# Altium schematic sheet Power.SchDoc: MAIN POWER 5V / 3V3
size A4; Date: Not used; ApprovedBy: Not used; CheckedBy: Not used; Author: Not used; CompanyName: STMicroelectronics; DrawnBy: Not used; Engineer: Not used; Organization: Not used; Address1: Not used; Address2: Not used; Address3: Not used; Address4: Not used; DocumentNumber: 6; Revision: Not used; SheetNumber: 6; SheetTotal: 8
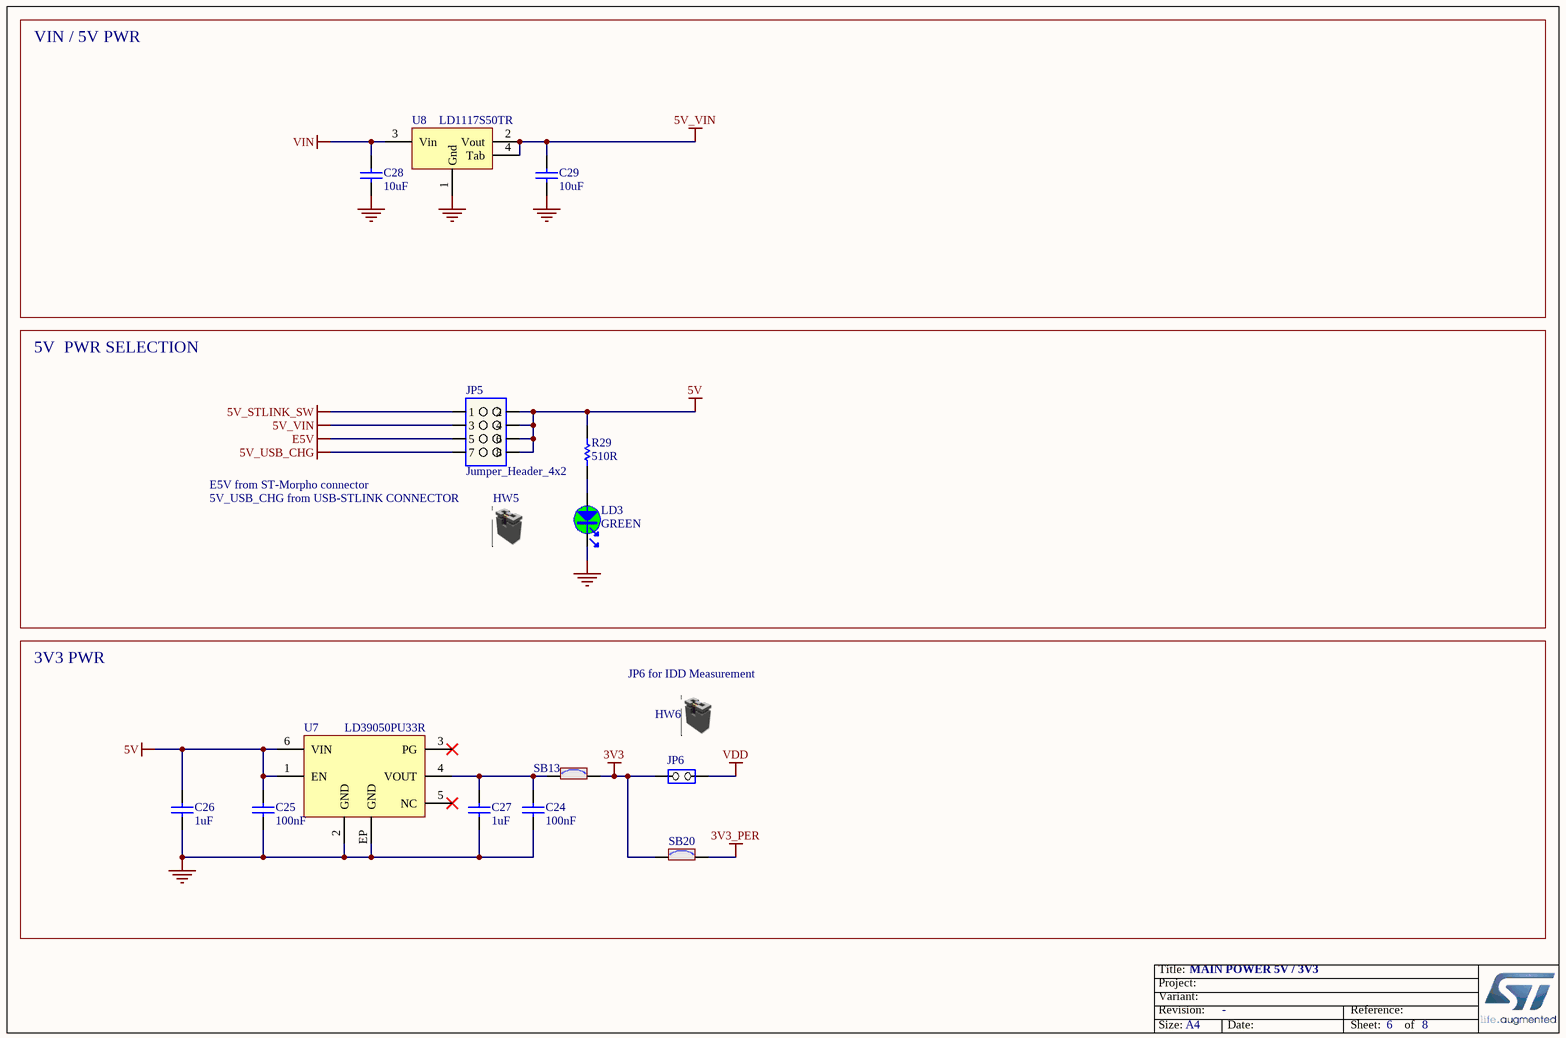
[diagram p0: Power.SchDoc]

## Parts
C24  value 100nF  [C0603]  (hidden comment: Capacitor)
C25  value 100nF  [C0603]  (hidden comment: Capacitor)
C26  value 1uF  [C0603]  (hidden comment: Capacitor)
C27  value 1uF  [C0603]  (hidden comment: Capacitor)
C28  value 10uF  [C0805]  (hidden comment: Capacitor)
C29  value 10uF  [C0805]  (hidden comment: Capacitor)
HW5  Shunt 2.54mm  [N/A]  (value not drawn)  (mechanical)
HW6  Shunt 2.54mm  [N/A]  (value not drawn)  (mechanical)
JP5  value Jumper_Header_4x2  [CON_SAMTEC_TSW-104-07-X-D]  (hidden comment: Jumper_Header 4x2)
JP6  Jumper Header 2x1  [CON_SAMTEC_TSW-102-07-G-S]  (value not drawn)
LD3  value GREEN  [LED_0603_GREEN]  (hidden comment: LED_green)
R29  value 510R  [R0603]  (hidden comment: Resistor)
SB13  SB_ON  [SOLDER-BRIDGE_R0603-0R]  (value not drawn)
SB20  SB_ON  [SOLDER-BRIDGE_R0603-0R]  (value not drawn)
U7  LD39050PU33R  [ICC_DFN6-EPAD_3X3_P095]
U8  LD1117S50TR  [REG_SOT223-TAB]

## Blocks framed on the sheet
VIN / 5V PWR: C28 C29 U8
5V  PWR SELECTION: HW5 JP5 LD3 R29
3V3 PWR: C24-C27 HW6 JP6 SB13 SB20 U7

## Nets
3V3: JP6.1(COMMON) SB13.2 SB20.1
3V3_PER: SB20.2
5V: C25.2 C26.2 JP5.2 JP5.4 JP5.6 JP5.8 R29.2 U7.1(EN) U7.6(VIN)
5V_STLINK_SW: JP5.1
5V_USB_CHG: JP5.7
5V_VIN: C29.2 JP5.3 U8.2(Vout) U8.4(Tab)
E5V: JP5.5
GND: C24.1 C25.1 C26.1 C27.1 C28.1 C29.1 LD3.2 U7.2(GND) U7.EP(GND) U8.1(Gnd)
VDD: JP6.2(NO)
VIN: C28.2 U8.3(Vin)
NetC24_2: C24.2 C27.2 SB13.1 U7.4(VOUT)
NetLD3_1: LD3.1 R29.1

Not connected (* = marked no-connect by the designer): U7 3(PG)* 5(NC)*

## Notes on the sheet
- E5V from ST-Morpho connector
- 5V_USB_CHG from USB-STLINK CONNECTOR
- (near HW6) JP6 for IDD Measurement

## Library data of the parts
C24 C25 = MCD-00237: Capacitor,100nF,6V3,X5R,10%,0603; Manufacturer_Part_Number: CC0603KRX5R5BB104; Manufacturer: YAGEO; Provided_By: Subcon; Initial_Board_Reference: mb1319
C26 C27 = MCD-00238: Capacitor,1uF,6V3,X5R,10%,0603; Manufacturer_Part_Number: CC0603KRX5R5BB105; Manufacturer: YAGEO; Provided_By: Subcon; Initial_Board_Reference: mb1319
C28 C29 = MCD-00014: Capacitor,10uF,25V,X5R,10%,0805; Manufacturer_Part_Number: C'0805KRX5R8BB106; Manufacturer: YAGEO; Provided_By: Subcon; Initial_Board_Reference: mb1274
HW5 HW6 = MCD-00043: SHUNT 2.54mm BLACK; Manufacturer_Part_Number: SNT-100-BK-G; Manufacturer: SAMTEC; Provided_By: Subcon
JP5 = MCD-00633: Header, 4x2, 2,54mm, VR, TH, Height 5.84mm/2.54mm; Part_Type: Connector; Manufacturer_Part_Number: TSW-104-07-x-D; Manufacturer: SAMTEC; Provided_By: Subcon; Initial_Board_Reference: mb1319
JP6 = MCD-00045: Header, 2x1, 2,54mm, VR, TH, Height 5.84mm/2.54mm; Manufacturer_Part_Number: TSW-102-07-x-S; Manufacturer: SAMTEC; Part_Type: Connector; Value: Jumper_Header_2x1; Provided_By: Subcon; Initial_Board_Reference: mb1274
LD3 = MCD-00050: LED, Green, 0603; Manufacturer_Part_Number: 19-213SYGC/S530-E2/TR8; Manufacturer: EVERLIGHT; Part_Type: Display; ECCN_US: EAR99; ECCN_EU: NEC; Provided_By: Subcon; Initial_Board_Reference: mb1274
R29 = MCD-00225: Resistor,510R,0603,1%,1/10W; Manufacturer_Part_Number: RC0603FR-07510RL; Manufacturer: YAGEO; Provided_By: Subcon; Initial_Board_Reference: mb1319
SB13 SB20 = MCD-00071: Solder Bridge ON; Part_Type: Mechanical; Provided_By: Subcon; Initial_Board_Reference: mb1274
U7 = MCD-00215: Low quiescent current and low noise voltage regulators; Manufacturer: STMICROELECTRONICS; Part_Type: IC; ECCN_US: EAR99; ECCN_EU: NEC; Provided_By: Subcon; Initial_Board_Reference: mb1319
U8 = MCD-00088: IC REG LDO 5V 0.8A SOT223; Manufacturer: STMICROELECTRONICS; ECCN_US: EAR99; ECCN_EU: NEC; Provided_By: Subcon; Initial_Board_Reference: mb1274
